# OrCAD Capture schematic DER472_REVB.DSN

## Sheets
1 PAGE2: size C
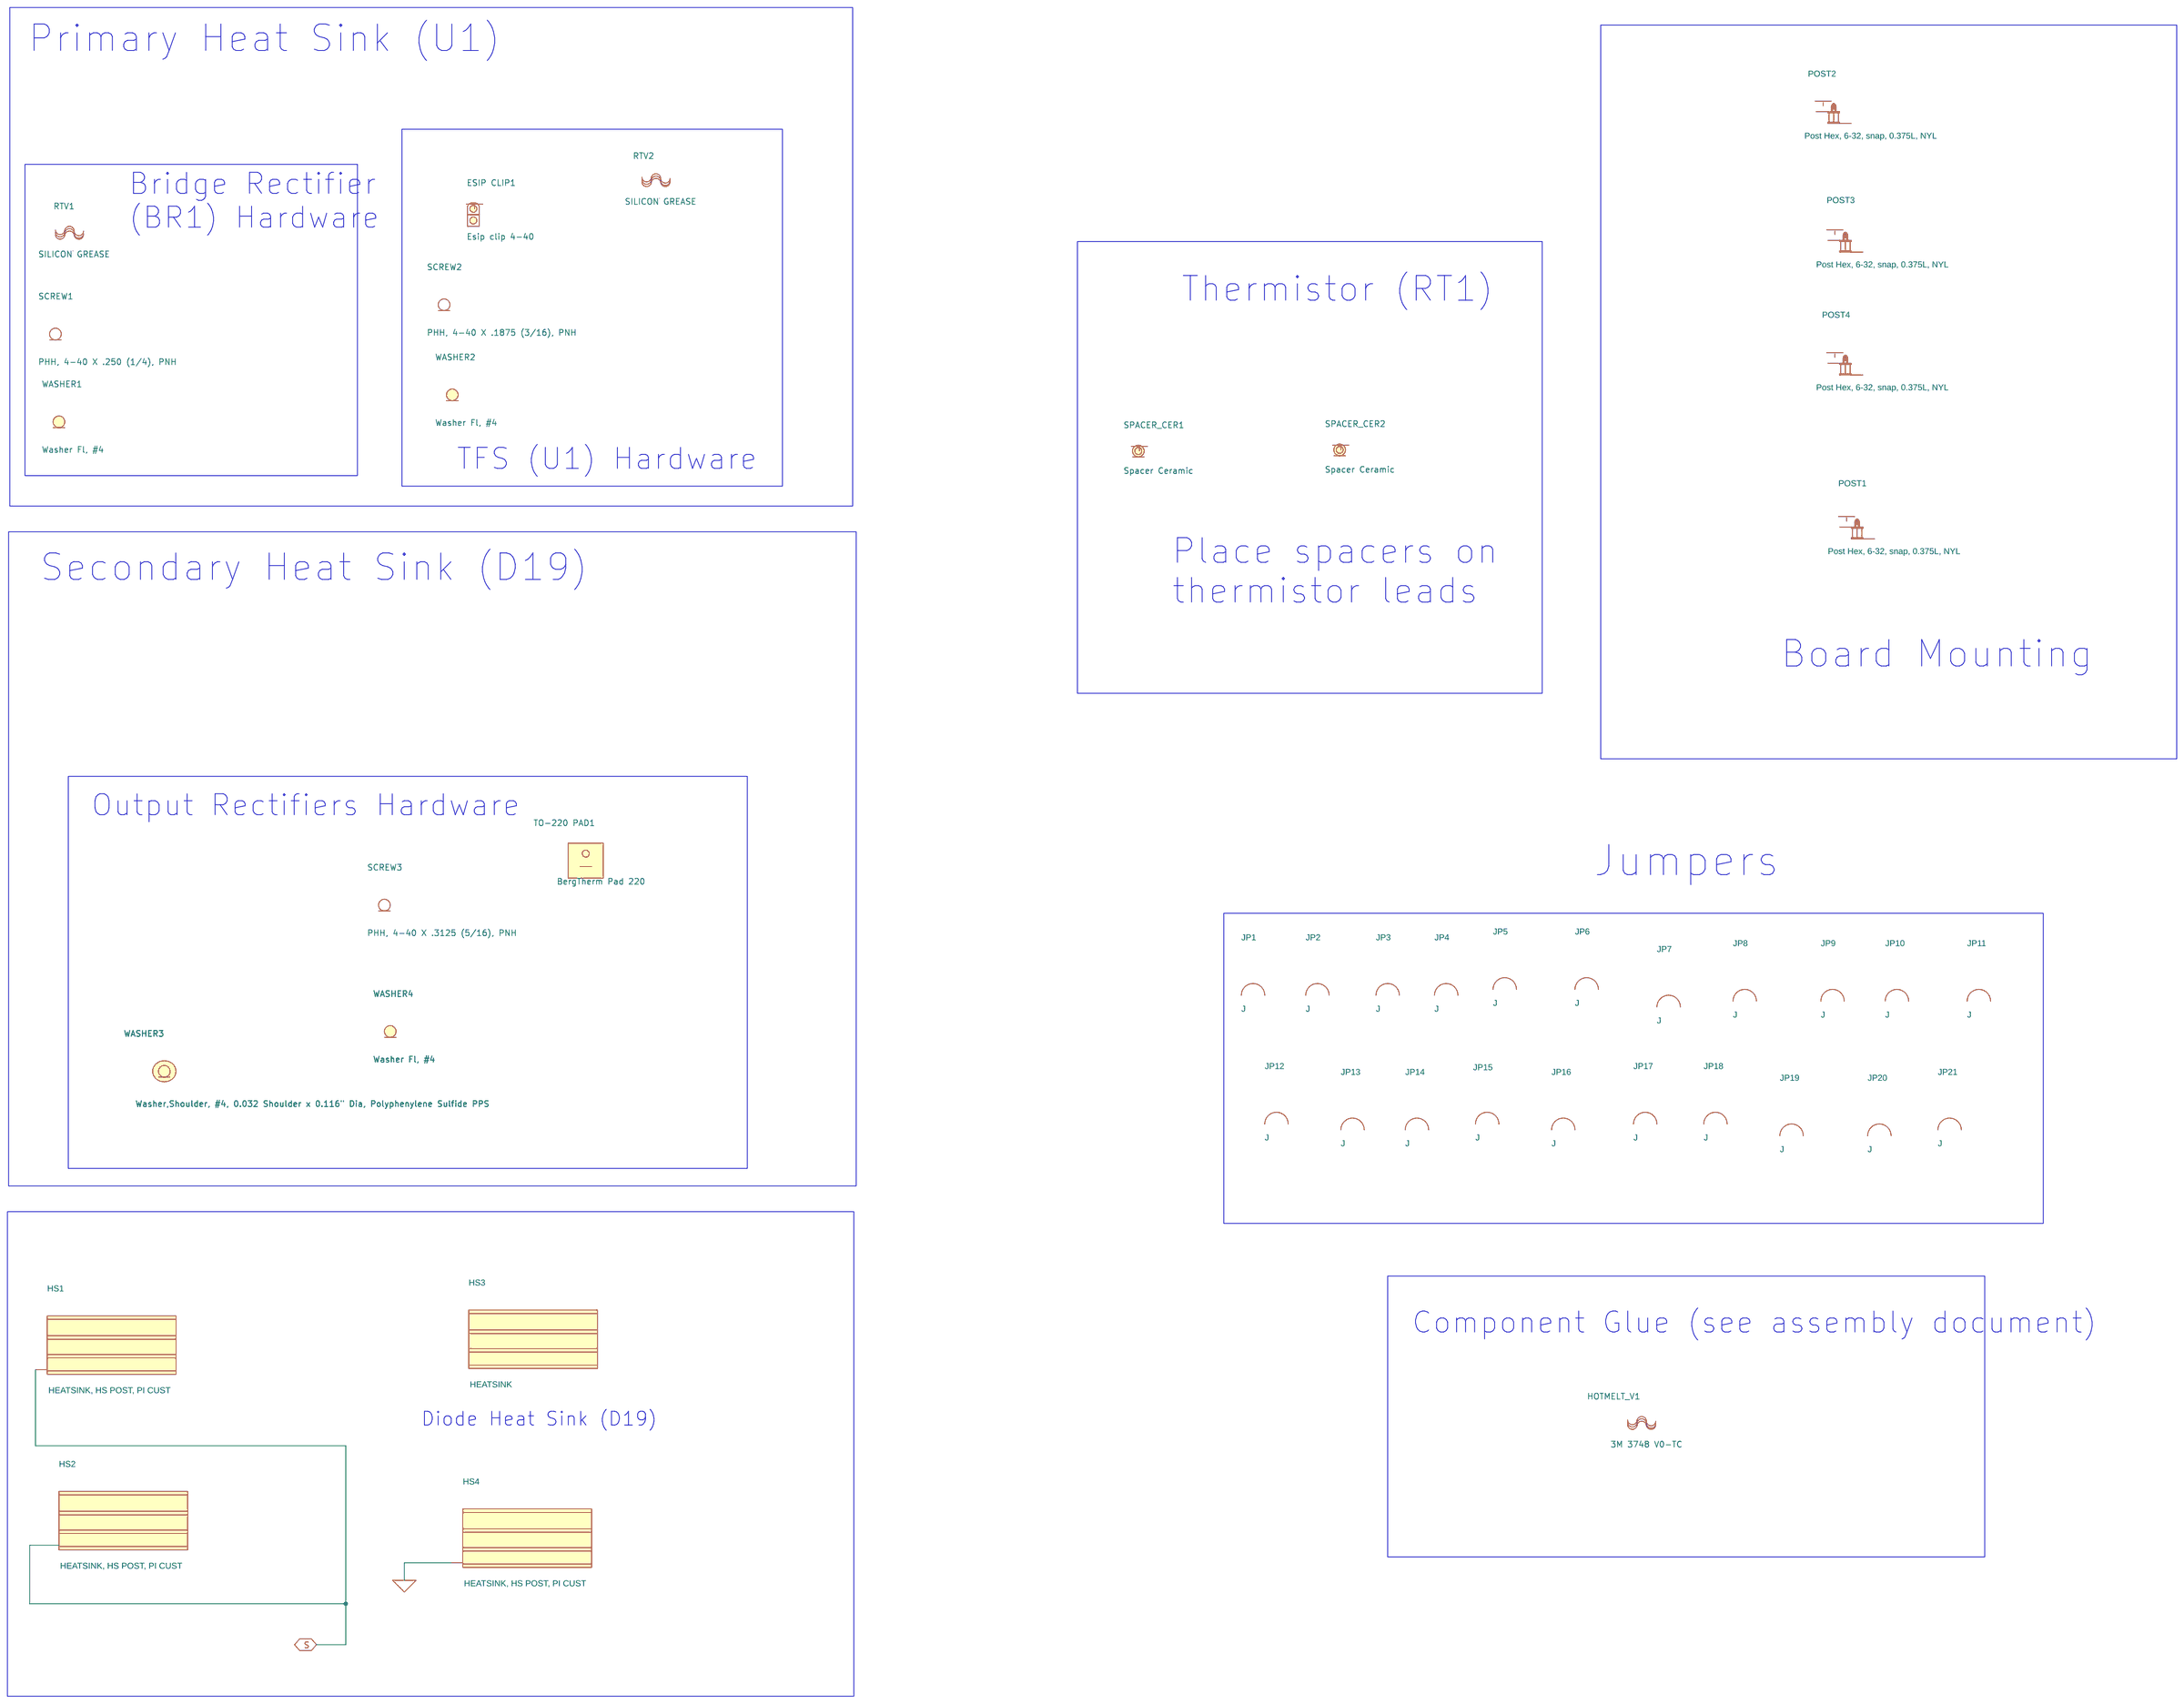
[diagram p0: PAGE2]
2 PAGE1: size C; title: DER-309; rev: A
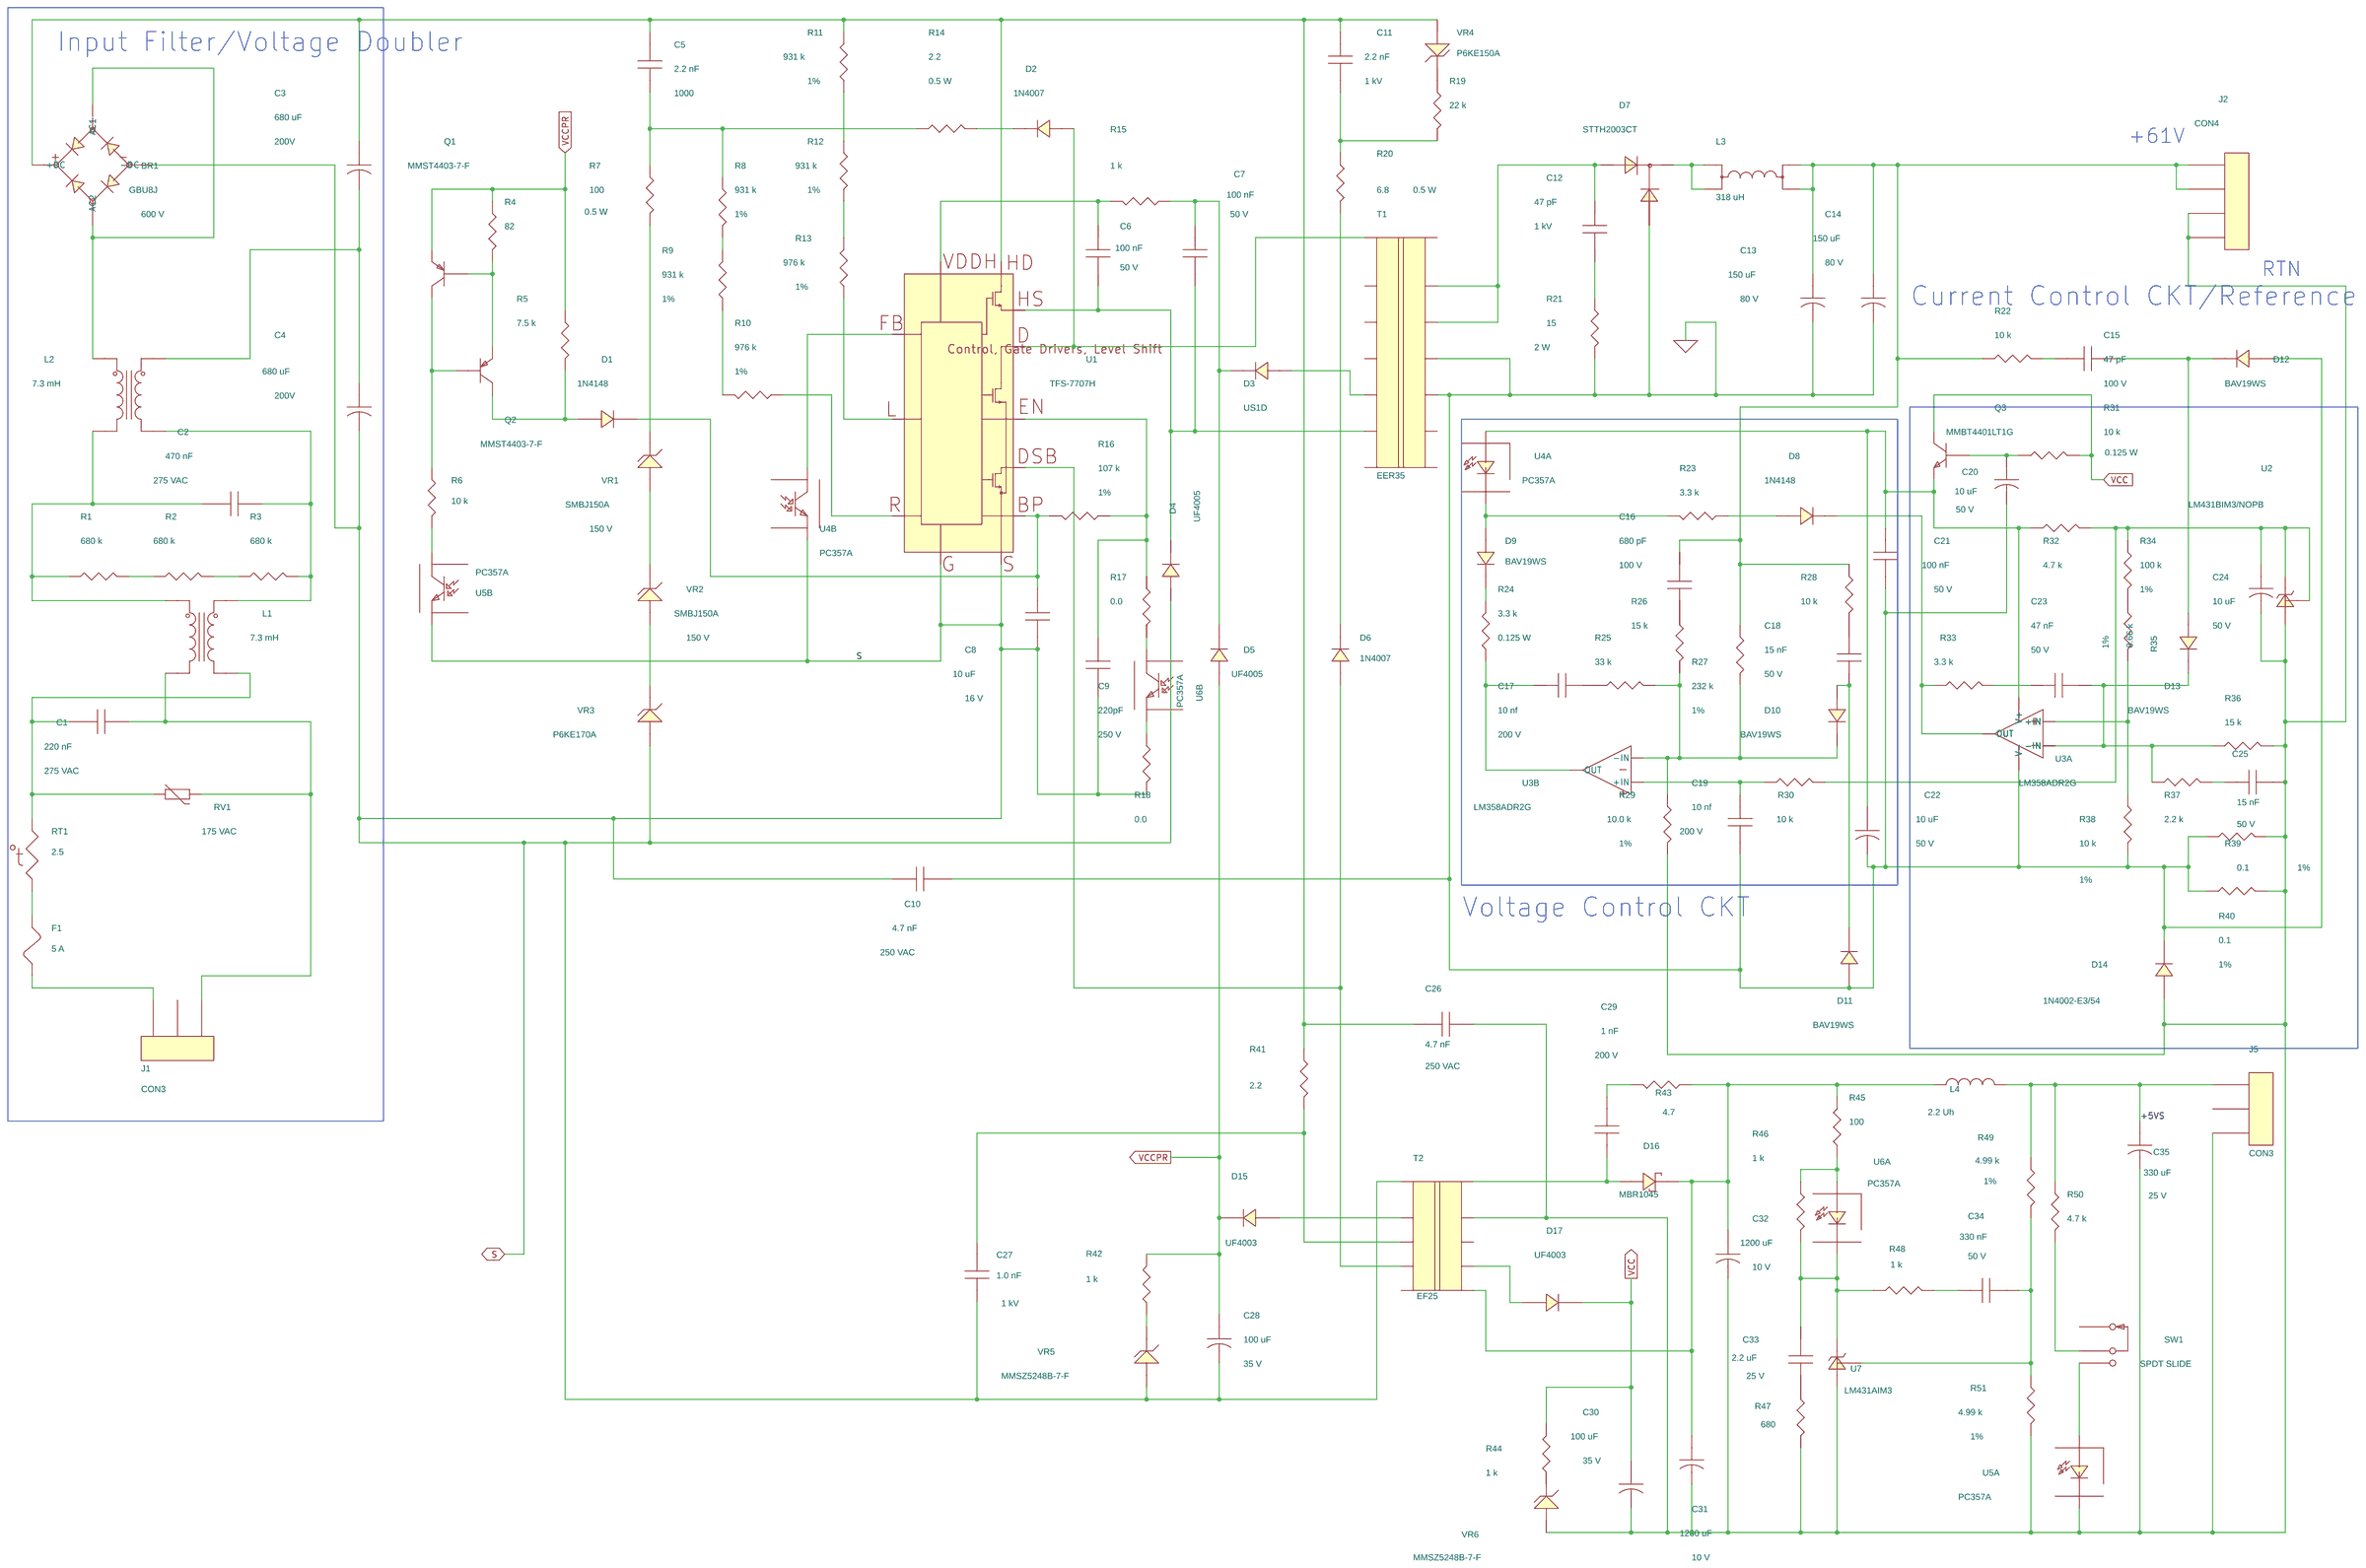
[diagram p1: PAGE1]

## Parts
sheet PAGE1
BR1  GBU8J  [pidaxbridgegbu8]
C1  220 nF  [pinpxcaprad720x340590040]
C2  470 nF  [pi_np_cap700x355ls600d040]
C3  680 uF  [pipolcapclyd948ls394080]
C4  680 uF  [pipolcapclyd948ls394080]
C5  2.2 nF  [pinpcaprad200x100200030]
C6  100 nF  [pismc0603]
C7  100 nF  [pismc0603]
C8  10 uF  [pinpcaprad200x100200030]
C9  220pF  [pismc0603]
C10  4.7 nF  [pinpcaprad640x260375040]
C11  2.2 nF  [pinpcaprad350x100200030]
C12  47 pF  [pinpcaprad180x160200030]
C13  150 uF  [pipolcapcyld400ls200040]
C14  150 uF  [pipolcapcyld400ls200040]
C15  47 pF  [pismc0805]
C16  680 pF  [pismc0603]
C17  10 nf  [pismc0805]
C18  15 nF  [pismc0805]
C19  10 nf  [pismc0805]
C20  10 uF  [pipolcapclyd200ls80030]
C21  100 nF  [pismc0805]
C22  10 uF  [pipolcapclyd200ls80030]
C23  47 nF  [pismc0805]
C24  10 uF  [pipolcapclyd200ls80030]
C25  15 nF  [pismc0805]
C26  4.7 nF  [pinpcaprad640x260375040]
C27  1.0 nF  [pinpcaprad290x160250030]
C28  100 uF  [pipolcapcyld250ls100030]
C29  1 nF  [pismc0805]
C30  100 uF  [pipolcapcyld250ls100030]
C31  1200 uF  [pipolcapcyld400ls200040]
C32  1200 uF  [pipolcapcyld400ls200040]
C33  2.2 uF  [pismc0805]
C34  330 nF  [pismc0805]
C35  330 uF  [pipolcapcyld400ls200040]
D1  1N4148  [pidax375x070030do35]
D2  1N4007  [pidax475x125040do41]
D3  US1D  [pismdsma]
D4  UF4005  [pidax475x125040do41]
D5  UF4005  [pidax475x125040do41]
D6  1N4007  [pidv200x110x040do41]
D7  STTH2003CT  [pidvto2203vf1]
D8  1N4148  [pidax375x070030do35]
D9  BAV19WS  [pismsod323]
D10  BAV19WS  [pismsod323]
D11  BAV19WS  [pismsod323]
D12  BAV19WS  [pismsod323]
D13  BAV19WS  [pismsod323]
D14  1N4002-E3/54  [pidv200x110x040do41]
D15  UF4003  [pidv200x110x040do41]
D16  MBR1045  [pidvt0220acreva]
D17  UF4003  [pidv200x110x040do41]
F1  5 A  [pi_tr5_submin_fuse]
J1  CON3  [pi_hdr_3pin]
J2  CON4  [PI_HDR_4PIN]
J5  CON3  [pi_hdr_3pin]
L1  7.3 mH  [piind4p1650x800ls900x600050]
L2  7.3 mH  [piind4p1650x800ls900x600050]
L3  318 uH  [pi_ind_4p_toroidal]
L4  2.2 Uh  [pi_choke_coilcraft_rfb0807]
Q1  MMST4403-7-F  [pismsot323132]
Q2  MMST4403-7-F  [pismsot323132]
Q3  MMBT4401LT1G  [pismsot23123_1]
R1  680 k  [pismr1206]
R2  680 k  [pismr1206]
R3  680 k  [pismr1206]
R4  82  [pismr0603]
R5  7.5 k  [pismr0603]
R6  10 k  [pismr0805]
R7  100  [pi12wvresd180ls150d040]
R8  931 k  [pismr1206]
R9  931 k  [pismr1206]
R10  976 k  [pismr1206]
R11  931 k  [pismr1206]
R12  931 k  [pismr1206]
R13  976 k  [pismr1206]
R14  2.2  [pi12wvresd180ls150d040]
R15  1 k  [pismr0603]
R16  107 k  [pi14wvresd100ls200d030]
R17  0.0  [pismr0805]
R18  0.0  [pismr0805]
R19  22 k  [pi14wvresd100ls100d030]
R20  6.8  [pi12wvresd180ls150d040]
R21  15  [pi2wvresd200ls300d040]
R22  10 k  [pismr0805]
R23  3.3 k  [pismr1206]
R24  3.3 k  [pi18wresd080ls300d030]
R25  33 k  [pismr0805]
R26  15 k  [pismr0805]
R27  232 k  [pismr0805]
R28  10 k  [pismr0805]
R29  10.0 k  [pi14wresd100ls400d030]
R30  10 k  [pismr1206]
R31  10 k  [pi18wvresd80ls100d030]
R32  4.7 k  [pismr0805]
R33  3.3 k  [pismr1206]
R34  100 k  [pismr0805]
R35  8.66 k  [pismr0603]
R36  15 k  [pi14wresd100ls400d030]
R37  2.2 k  [pismr0805]
R38  10 k  [pismr0805]
R39  0.1  [pismr2512]
R40  0.1  [pismr2512]
R41  2.2  [pi12wvresd180ls150d040]
R42  1 k  [pismr0805]
R43  4.7  [pismr1206]
R44  1 k  [pismr0805]
R45  100  [pismr0805]
R46  1 k  [pismr0805]
R47  680  [pismr0805]
R48  1 k  [pismr0805]
R49  4.99 k  [pismr0805]
R50  4.7 k  [pismr0805]
R51  4.99 k  [pismr0805]
RT1  2.5  [pi_rad185x610ls300d031]
RV1  175 VAC  [pi_disc_575x320_ls335x140d040]
SW1  SPDT SLIDE  [pi_switch_spdt_slide_pcbm_1]
T1  EER35  [pi_bobbin_eer35_14p]
T2  EF25  [pi_bobbin_ef25_10p]
U1  TFS-7707H  [pi_ic_esip16-12_oval_slot_recpt]
U2  LM431BIM3/NOPB  [pismsot23123]
U3  LM358ADR2G  [pismso8]  (sections A,B)
U4  PC357A  [pi_4_smd]  (sections A,B)
U5  PC357A  [pi_4_smd]  (sections A,B)
U6  PC357A  [pi_4_smd]  (sections A,B)
U7  LM431AIM3  [pismsot23123]
VR1  SMBJ150A  [pismdo214aa12]
VR2  SMBJ150A  [pismdo214aa12]
VR3  P6KE170A  [pidax550x140050do15do204ac]
VR4  P6KE150A  [pidv200x140x050do15do204ac]
VR5  MMSZ5248B-7-F  [pi_sm_sod-123_12]
VR6  MMSZ5248B-7-F  [pi_sm_sod-123_12]
sheet PAGE2
ESIP CLIP1  Esip clip 4-40
HOTMELT_V1  3M 3748 V0-TC
HS1  HEATSINK, HS POST, PI CUST  [pi_hs_der472_bridge]
HS2  HEATSINK, HS POST, PI CUST  [pi_hs_der472_eSIP]
HS3  HEATSINK  [pi_hs_TO220_vert]
HS4  HEATSINK, HS POST, PI CUST  [pi_hs_der472_diode]
JP1  J  [pi_jumper500]
JP2  J  [pi_jumper500]
JP3  J  [pi_jumper300]
JP4  J  [pi_jumper400]
JP5  J  [pi_jumper600]
JP6  J  [pi_jumper600-18awg-sld]
JP7  J  [pi_jumper1100-18awg-sld]
JP8  J  [pi_jumper500]
JP9  J  [pi_jumper500]
JP10  J  [pi_jumper1100]
JP11  J  [pi_jumper300]
JP12  J  [pi_jumper800-18awg-sld]
JP13  J  [pi_jumper300]
JP14  J  [pi_jumper700]
JP15  J  [pi_jumper300]
JP16  J  [pi_jumper600-18awg-sld]
JP17  J  [pi_jumper300]
JP18  J  [pi_jumper800]
JP19  J  [pi_jumper1000]
JP20  J  [pi_jumper200]
JP21  J  [pi_jumper800-18awg-sld]
POST1  Post Hex, 6-32, snap, 0.375L, NYL  [pimtgholed156]
POST2  Post Hex, 6-32, snap, 0.375L, NYL  [pimtgholed156]
POST3  Post Hex, 6-32, snap, 0.375L, NYL  [pimtgholed156]
POST4  Post Hex, 6-32, snap, 0.375L, NYL  [pimtgholed156]
RTV1  SILICON GREASE
RTV2  SILICON GREASE
SCREW1  PHH, 4-40 X .250 (1/4), PNH
SCREW2  PHH, 4-40 X .1875 (3/16), PNH
SCREW3  PHH, 4-40 X .3125 (5/16), PNH
SPACER_CER1  Spacer Ceramic
SPACER_CER2  Spacer Ceramic
TO-220 PAD1  BergTherm Pad 220
WASHER1  Washer Fl, #4
WASHER2  Washer Fl, #4
WASHER3  Washer,Shoulder, #4, 0.032 Shoulder x 0.116" Dia, Polyphenylene Sulfide PPS
WASHER4  Washer Fl, #4

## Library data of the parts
BR1 = DISCRETE_BRIDGE_+~~-: Disp_Voltage: 600 V; Part Number: 15-00720-00
C1 = CAP_NP: Disp_Voltage: 275 VAC; Part Number: 20-00386-00; Voltage: 275 VAC
C2 = CAP_NP: COMPGROUP: 1; Disp_Voltage: 275 VAC; PCB Editor PCBFP: pinpxcaprad720x340590040; Part Number: 20-01169-00; Tol: 20; Voltage: 275 VAC
C3 C4 = CAP_POL: Disp_Voltage: 200V; Part Number: 20-08926-00; Voltage: 200V
C5 = CAP_NP: Disp_Voltage: 1000; Part Number: 20-01093-00; Voltage: 1000
C6 C7 = CAP_NP: Disp_Voltage: 50 V; Part Number: 20-00936-00; Voltage: 50 V
C8 = CAP_NP: Disp_Voltage: 16 V; Part Number: 20-01172-00; Voltage: 16 V
C9 = CAP_NP: Disp_Voltage: 250 V; Part Number: 20-00840-00; Voltage: 250 V
C10 C26 = CAP_NP: Disp_Voltage: 250 VAC; Part Number: 20-00378-00; Voltage: 250 VAC
C11 = CAP_NP: Disp_Voltage: 1 kV; Part Number: 20-00357-00; Voltage: 1 kV
C12 = CAP_NP: Disp_Voltage: 1 kV; Part Number: 20-00668-00; Voltage: 1 kV
C13 C14 = CAP_POL: Disp_Voltage: 80 V; Part Number: 20-08911-00; Voltage: 80 V
C15 = CAP_NP: Disp_Voltage: 100 V; Part Number: 20-00582-00; Voltage: 100 V
C16 = CAP_NP: Disp_Voltage: 100 V; Part Number: 20-08597-00; Voltage: 100 V
C17 C19 = CAP_NP: Disp_Voltage: 200 V; Part Number: 20-00531-00; Voltage: 200 V
C18 C25 = CAP_NP: Disp_Voltage: 50 V; Part Number: 20-00223-00; Voltage: 50 V
C20 C22 C24 = CAP_POL: ALT_SYMBOLS: pipolcapclyd200ls80030h; Disp_Voltage: 50 V; FPLIST: pipolcapclyd200ls80030,pipolcapclyd200ls80030h; Part Number: 20-00443-00; Voltage: 50 V
C21 = CAP_NP: Disp_Voltage: 50 V; Part Number: 20-00904-00; Voltage: 50 V
C23 = CAP_NP: Disp_Voltage: 50 V; Part Number: 20-00964-00; Voltage: 50 V
C27 = CAP_NP: Disp_Voltage: 1 kV; Part Number: 20-00662-00; Voltage: 1 kV
C28 C30 = CAP_POL: ALT_SYMBOLS: pipolcapclyd250ls100d30h590; COMPGROUP: 1; Disp_Voltage: 35 V; FPLIST: pipolcapcyld250ls100030,pipolcapclyd250ls100d30h590; Part Number: 20-00117-00; Tol: 20; Voltage: 35 V
C29 = CAP_NP: Disp_Voltage: 200 V; Part Number: 20-00737-00; Voltage: 200 V
C31 C32 = CAP_POL: Disp_Voltage: 10 V; Part Number: 23-00060-00; Voltage: 10V
C33 = CAP_NP: Disp_Voltage: 25 V; Part Number: 20-08603-00; Voltage: 25 V
C34 = CAP_NP: Disp_Voltage: 50 V; Part Number: 20-00895-00; Voltage: 50 V
C35 = CAP_POL: ALT_SYMBOLS: pipolcapclyd400x530ls200030h; Disp_Voltage: 25 V; Part Number: 20-00100-00; Voltage: 25 V
D1 D8 = DIODE: ALT_SYMBOLS: pidax375x070030do35,pidv100x080x030do35; FPLIST: pidv200x080x030do35,pidax375x070030do35,pidv100x080x030do35; Part Number: 15-00083-00
D2 D6 = DIODE: ALT_SYMBOLS: pidax475x125040do41,pidv200x110x040do41wbead,pidax390x125040do41; FPLIST: pidv200x110x040do41,pidax475x125040do41,pidv200x110x040do41wbead,pidax390x125040do41; Part Number: 15-00623-00
D3 = DIODE: Part Number: 15-00492-00
D4 D5 = DIODE: ALT_SYMBOLS: pidax475x125040do41,pidax390x125040do41; FPLIST: pidv200x110x040do41,pidax475x125040do41,pidax390x125040do41; Part Number: 15-00109-00
D7 = D_DUAL_CK_ACA_3: FPLIST: pidvto2203,pidvto2203vf1; Part Number: 15-01131-00
D9-D13 = DIODE: Part Number: 15-00658-00
D14 = DIODE: ALT_SYMBOLS: pidax475x125040do41,pidv200x110x040do41wbead,pidax390x125040do41; FPLIST: pidv200x110x040do41,pidax475x125040do41,pidv200x110x040do41wbead,pidax390x125040do41; Part Number: 15-00792-00
D15 D17 = DIODE: ALT_SYMBOLS: pidax475x125040do41,pidv200x110x040do41wbead,pidax390x125040do41; COMPGROUP: 1; FPLIST: PI_DV/.200X.110X.040/DO_41,PI_DAX/.475X.125/.040/DO_41,PI_DV/.200X.110X.040/DO_41_WBEAD,PI_DAX/.390X.125/.040/DO_41; Part Number: 15-00107-00
D16 = DIODE_SCHOTTKY: Part Number: 15-00147-00
F1 = FUSE: COMPGROUP: 1; Part Number: 40-00005-00; Voltage: 250 V
J1 = CON3: COMPGROUP: 1; Part Number: 35-00002-00
J2 = CON4: COMPGROUP: 2; Part Number: 35-00003-00
J5 = CON3: Part Number: 35-00002-00
L1 L2 = INDUCTOR_4P_revD: Part Number: 30-00404-00
L3 = INDUCTOR_4P_SD: Part Number: 32-00319-00
L4 = INDUCTOR: Part Number: 30-00161-00
Q1 Q2 = PNP_BEC: Part Number: 55-00064-00
Q3 = NPN_BEC: Part Number: 55-00059-00
R1-R3 = R: Part Number: 05-01420-00
R4 = R: Part Number: 05-01662-00
R5 = R: Part Number: 05-01709-00
R6 R22 R28 = R: Part Number: 05-01543-00
R7 = R: ALT_SYMBOLS: pi12wvresd180ls200d040,pi12wvresd180ls250d040,pi12wresd180ls675d040; Disp_Power: 0.5 W; FPLIST: pi12wvresd180ls150d040,pi12wvresd180ls200d040,pi12wvresd180ls250d040,pi12wresd180ls675d040; Part Number: 05-05569-00
R8 R9 R11 = R: Disp_Tol: 1%; Part Number: 05-00478-00
R10 = R: Disp_Tol: 1%; Part Number: 05-00480-00
R12 = R: COMPGROUP: 2; Disp_Tol: 1%; Part Number: 05-00478-00; Tol: 1%
R13 = R: COMPGROUP: 2; Disp_Tol: 1%; Part Number: 05-00480-00; Tol: 1%
R14 = R: ALT_SYMBOLS: pi12wvresd180ls200d040,pi12wvresd180ls250d040,pi12wresd180ls675d040; Disp_Power: 0.5 W; FPLIST: pi12wvresd180ls150d040,pi12wvresd180ls200d040,pi12wvresd180ls250d040,pi12wresd180ls675d040; Part Number: 05-02611-00
R15 = R: COMPGROUP: 2; PCB Editor PCBFP: pismr0805; Part Number: 05-01688-00; Tol: 5%
R16 = R: ALT_SYMBOLS: pi14wvresd100ls200d030,pi14wresd100ls400d030,pi14wresd100ls500d030; Disp_Tol: 1%; FPLIST: pi14wvresd100ls100d030,pi14wvresd100ls200d030,pi14wresd100ls400d030,pi14wresd100ls500d030; Part Number: 05-02171-00
R17 R18 = R: Part Number: 05-03159-00
R19 = R: ALT_SYMBOLS: pi14wvresd100ls200d030,pi14wresd100ls400d030,pi14wresd100ls500d030; FPLIST: pi14wvresd100ls100d030,pi14wvresd100ls200d030,pi14wresd100ls400d030,pi14wresd100ls500d030; Part Number: 05-02539-00
R20 = R: ALT_SYMBOLS: pi12wvresd180ls200d040,pi12wvresd180ls250d040,pi12wresd180ls675d040; Disp_Power: 0.5 W; FPLIST: pi12wvresd180ls150d040,pi12wvresd180ls200d040,pi12wvresd180ls250d040,pi12wresd180ls675d040; Part Number: 05-02623-00
R21 = R: ALT_SYMBOLS: pi2wresd200ls900d040,pi2wvresd200ls300d040,pi2wvresd200ls400d040; Disp_Power: 2 W; FPLIST: pi2wresd200ls725d040,pi2wresd200ls900d040,pi2wvresd200ls300d040,pi2wvresd200ls400d040; Part Number: 05-02960-00
R23 R33 = R: Part Number: 05-01364-00
R24 = R: Disp_Power: 0.125 W; FPLIST: pi18wvresd80ls100d030,pi18wresd080ls300d030; Part Number: 05-02349-00
R25 = R: Part Number: 05-01555-00
R26 = R: Part Number: 05-01547-00
R27 = R: Disp_Tol: 1%; Part Number: 05-00815-00
R29 = R: ALT_SYMBOLS: pi14wvresd100ls200d030,pi14wresd100ls400d030,pi14wresd100ls500d030; Disp_Tol: 1%; FPLIST: pi14wvresd100ls100d030,pi14wvresd100ls200d030,pi14wresd100ls400d030,pi14wresd100ls500d030; Part Number: 05-05421-00
R30 = R: Part Number: 05-01376-00
R31 = R: ALT_SYMBOLS: pi18wresd080ls300d030; Disp_Power: 0.125 W; FPLIST: pi18wvresd80ls100d030,pi18wresd080ls300d030; Part Number: 05-02361-00
R32 R50 = R: Part Number: 05-01535-00
R34 = R: Disp_Tol: 1%; Part Number: 05-00780-00
R35 = R: Disp_Tol: 1%; Part Number: 05-01168-00
R36 = R: ALT_SYMBOLS: pi14wvresd100ls200d030,pi14wresd100ls400d030,pi14wresd100ls500d030; COMPGROUP: 5; FPLIST: pi14wvresd100ls100d030,pi14wvresd100ls200d030,pi14wresd100ls400d030,pi14wresd100ls500d030; PCB Editor PCBFP: pismr0805; Part Number: 05-02535-00; Tol: 1%
R37 = R: Part Number: 05-01527-00
R38 = R: Disp_Tol: 1%; Part Number: 05-00684-00
R39 R40 = R: Disp_Tol: 1%; Part Number: 05-06320-00
R41 = R: ALT_SYMBOLS: pi12wvresd180ls200d040,pi12wvresd180ls250d040,pi12wresd180ls675d040; FPLIST: pi12wvresd180ls150d040,pi12wvresd180ls200d040,pi12wvresd180ls250d040,pi12wresd180ls675d040; Part Number: 05-05578-00
R42 R44 R46 R48 = R: Part Number: 05-01519-00
R43 = R: Part Number: 05-01296-00
R45 = R: Part Number: 05-01495-00
R47 = R: Part Number: 05-01515-00
R49 R51 = R: Disp_Tol: 1%; Part Number: 05-03373-00
RT1 = THERMISTOR: ALT_SYMBOLS: pi_np_ycap_rad600ls400d040_h; FPLIST: pi_rad185x610ls300d031,pi_np_ycap_rad600ls400d040_h; Part Number: 90-00036-00
RV1 = VARISTOR: COMPGROUP: 1; Part Number: 85-00029-00
SW1 = SW_SLIDE-SPDT: Part Number: 66-00111-00
T1 = BEER35_14P_GENERIC: Part Number: 25-00029-00
T2 = BF25_10P_GENERIC: Part Number: 25-00012-01
U1 = HiperTFS_II_I_2_ROW: FPLIST: pi_ic_esip16-12_oval_slot,pi_ic_esip16-12_oval_slot_recpt; Part Number: 10-00612-00
U2 = TL431_SOT-23_CAR: Part Number: 45-00232-00
U3 = LM358: Part Number: 45-00316-00
U4-U6 = OPTO_A_B: Part Number: 53-00003-00
U7 = TL431_SOT-23_CAR: Part Number: 45-00268-00
VR1 VR2 = DIODE_ZENER: Disp_Voltage: 150 V; Part Number: 15-00427-00
VR3 = DIODE_ZENER: FPLIST: pidv200x140x050do15do204ac,pidax550x140050do15do204ac; Part Number: 15-00617-00
VR4 = DIODE_ZENER: ALT_SYMBOLS: pidax550x140050do15do204ac; FPLIST: pidv200x140x050do15do204ac,pidax550x140050do15do204ac; Part Number: 15-00619-00
VR5 VR6 = DIODE_ZENER: Part Number: 15-01105-00
ESIP CLIP1 = EsipClip_4-40: Part Number: 60-00037-00
HOTMELT_V1 = HOTMELT-V0: Part Number: 66-00077-00
HS1 = HS-PI_CUSTOM1: Part Number: 61-00193-01
HS2 = HS-PI_CUSTOM2: Part Number: 61-00201-01
HS3 = HS-PI_CUSTOM2: Part Number: 60-00093-00
HS4 = HS-PI_CUSTOM1: Part Number: 61-00194-01
JP1 JP2 JP8 JP9 = JUMPER_1: Part Number: 65-00122-00
JP3 JP11 JP13 JP15 JP17 = JUMPER_1: Part Number: 65-00120-00
JP4 = JUMPER_1: Part Number: 65-00121-00
JP5 = JUMPER_1: Part Number: 65-00123-00
JP6 JP16 = JUMPER_1: Part Number: 65-00084-00
JP7 = JUMPER_1: Part Number: 65-00089-00
JP10 = JUMPER_1: Part Number: 65-00128-00
JP12 JP21 = JUMPER_1: Part Number: 65-00086-00
JP14 = JUMPER_1: Part Number: 65-00124-00
JP18 = JUMPER_1: Part Number: 65-00125-00
JP19 = JUMPER_1: Part Number: 65-00127-00
JP20 = JUMPER_1: Part Number: 65-00119-00
POST1-POST4 = POST_CRKT_BRD_6-32_HEX: Part Number: 76-00003-00
RTV1 RTV2 = RTV: Part Number: 66-00084-00
SCREW1 = SCR_4-40: Part Number: 75-00001-00
SCREW2 = SCR_4-40: Part Number: 75-00089-00
SCREW3 = SCR_4-40: Part Number: 75-00002-00
SPACER_CER1 SPACER_CER2 = Spacer_Ceramic: Part Number: 76-00031-00
TO-220 PAD1 = Berguist_TO-220_Pad: Part Number: 66-00079-00
WASHER1 = WASH_FLAT_4: Part Number: 75-00032-00
WASHER2 WASHER4 = WASH_FLAT_4: Part Number: 75-00164-00
WASHER3 = WASH_SHLDR_4: Part Number: 75-00152-00

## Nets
+5VS: C35.1 J5.1 L4.2 R49.1 R50.1
GND_SIGNAL: C10.2 C13.2 C14.2 C19.2 C20.2 C21.2 C22.2 D7.1(A1) D11.2 D12.2 D14.1 HS4.1 R21.2 R38.2 R39.1 R40.1 T1.10 T1.11 U3.4(V-)
VCC: C30.1 D17.1 Q3.3(COLLECTOR) R31.2 R44.2
VCCPR: C28.1 D5.2 D15.1 Q1.2(EMITTER) R4.2 R5.2 R42.2
S: BR1.4(-DC) C4.2 C8.2 C9.2 C10.1 C27.1 C28.2 D4.2 HS1.1 HS2.1 R18.2 T2.1 U1.5(G) U1.6(S) U4.3(E) U5.3(E) VR3.2 VR5.2
N6240208: R12.2 R13.2
N6900286: BR1.1(+DC) C3.1 C5.2 C11.1 C26.2 R11.2 R41.1 U1.16(HD) VR4.2
N7091362: C13.1 C14.1 C16.2 J2.1 J2.2 L3.3 L3.4 R22.1 R27.1 R28.1
N7093005: C24.2 C25.2 C26.1 C30.2 C31.2 C32.2 C35.2 D14.2 J2.3 J2.4 J5.3 R29.2 R36.2 R39.2 R40.2 R47.2 R51.2 T2.9 U2.2(A) U5.2(C) U7.2(A) VR6.2
N8059193: C1.2 L1.3 RT1.2 RV1.1
N8059197: F1.1 J1.1
N8059233: C2.1 L1.4 L2.3 R3.2
N8059379: R1.2 R2.1
N8059399: R2.2 R3.1
N8059437: C1.1 J1.3 L1.2 RV1.2
N8059489: C2.2 L1.1 L2.2 R1.1
N8060888: BR1.2(AC1) BR1.3(AC2) L2.1
N8070346: C24.1 R30.2 R32.2 R34.1 U2.1(C) U2.3(VREF)
N8070490: D8.1 R33.1 U3.1(OUT)
N8071028: R35.2 R38.1 U3.3(+IN)
N8073566: C3.2 C4.1 L2.4
N8088388: F1.2 RT1.1
N8130547: R50.2 SW1.2
N8194184: C6.2 C7.2 D4.1 T1.6 U1.14(HS)
N8194788: D2.2 T1.1 U1.1(D)
N8195114: C9.1 R16.2 R17.1 U1.8(EN)
N8203204: C12.1 D7.3(A2) T1.12 T1.13
N8207135: C7.1 D3.1 D5.1 R15.2
N8207503: C6.1 R15.1 U1.13(VDDH)
N8207747: C8.1 D1.1 R16.1 U1.11(BP)
N8210629: C11.2 R19.2 R20.1
N8210678: D6.1 R20.2
N8215309: R9.2 R10.2
N8245190: R11.1 R12.1
N8282330: VR1.2 VR2.1
N8282334: C5.1 R7.2 R8.1 R14.1
N8284357: R7.1 VR1.1
N8290901: C12.2 R21.1
N8293124: D7.2(CATHODE) L3.1 L3.2
N8295742: R8.2 R9.1
N8307586: D2.1 R14.2
N8312021: D1.2 Q2.3(COLLECTOR) R5.1
N8340111: R6.1 U5.4(C)
N8340115: Q1.3(COLLECTOR) Q2.1(BASE) R6.2
N8340130: Q1.1(BASE) Q2.2(EMITTER) R4.1
N8345149: C33.2 R46.2 R48.1 U6.2(C) U7.1(C)
N8345153: R45.1 R46.1 U6.1(A)
N8345627: C31.1 C32.1 D16.1 L4.1 R43.1 R45.2 T2.6
N8345631: C29.1 D16.2 T2.10
N8345647: C34.2 R49.2 R51.1 U7.3(VREF)
N8350160: D3.2 T1.5
N8355512: D8.2 R23.1
N8356324: C21.1 C22.1 Q3.2(EMITTER) R32.1 U3.8(V+) U4.1(A)
N8356492: SW1.3 U5.1(A)
N8357362: C27.2 R41.2 T2.3
N8357377: D6.2 T2.4 U1.3(DSB)
N8358236: C29.2 R43.2
N8360452: VR2.2 VR3.1
N8378806: C34.1 R48.2
N8386529: C23.1 R33.2
N8402614: R10.1 U1.7(R)
N8402673: R13.1 U1.9(L)
N8403112: U1.10(FB) U4.4(C)
N8443298: R42.1 VR5.1
N8443789: D17.2 T2.7
N8454150: R44.1 VR6.1
N8457796: C18.1 D10.2 D11.1
N8460852: C17.1 R24.1 U3.7(OUT)
N8461930: D9.1 R24.2
N8461934: D9.2 R23.2 U4.2(C)
N8468098: C23.2 D13.1 R36.1 R37.1 U3.2(-IN)
N8468110: C15.1 D12.1 D13.2
N8468169: C15.2 R22.2
N8482095: D10.1 R25.2 R26.2 R27.2 R29.1 U3.6(-IN)
N8483580: C19.1 R30.1 U3.5(+IN)
N8501940: C20.1 Q3.1(BASE) R31.1
N8525050: D15.2 T2.2
N8535861: R17.2 U6.4(C)
N8535880: R18.1 U6.3(E)
N8557086: C25.1 R37.2
N8572111: R19.1 VR4.1
N8572265: C17.2 R25.1
N8572286: C16.1 R26.1
N8572381: C18.2 R28.2
N8572637: R34.2 R35.1
N8573402: C33.1 R47.1

Not connected (* = marked no-connect by the designer): HS2 2; HS3 1 2; J1 2; J5 2; JP1 1 2; JP2 1 2; JP3 1 2; JP4 1 2; JP5 1 2; JP6 1 2; JP7 1 2; JP8 1 2; JP9 1 2; JP10 1 2; JP11 1 2; JP12 1 2; JP13 1 2; JP14 1 2; JP15 1 2; JP16 1 2; JP17 1 2; JP18 1 2; JP19 1 2; JP20 1 2; JP21 1 2; POST1 1; POST2 1; POST3 1; POST4 1; SW1 1; T1 2 3 4 7 8 9 14; T2 5 8

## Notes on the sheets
sheet 1
- Primary Heat Sink (U1)
- Bridge Rectifier
  (BR1) Hardware
- Thermistor (RT1)
- TFS (U1) Hardware
- Place spacers on
  thermistor leads
- Secondary Heat Sink (D19)
- Board Mounting
- Output Rectifiers Hardware
- Jumpers
- Component Glue (see assembly document)
- Diode Heat Sink (D19)
sheet 2
- Input Filter/Voltage Doubler
- +61V
- RTN
- Current Control CKT/Reference
- Voltage Control CKT
